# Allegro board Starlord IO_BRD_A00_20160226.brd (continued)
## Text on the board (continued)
User.28: ByImpedance:100.0@_REF_L1=("nil(L1)")|_REF_L6=("4.0/10.0(L6)")|Type="DP"|_REF_L4=("4.0/6.5(L4)")|_REF_L3=("4.0/6.5(L3)" "4.0/10.0(L3)")|imp="100.0"|_REF_L8=("nil(L8)") | ByImpedance:33.0@_REF_L1=("8.0(L1)")|_REF_L6=("9.0(L6)")|Type="SE"|_REF_L4=("11.0(L4)")|_REF_L3=("11.0(L3)" "9.0(L3)")|imp="33.0"|_REF_L8=("8.0(L8)") | ByImpedance:35.0@_REF_L1=("7.5(L1)")|_REF_L6=("8.5(L6)")|Type="SE"|_REF_L4=("10.0(L4)")|_REF_L3=("10.0(L3)" "8.5(L3)")|imp="35.0"|_REF_L8=("7.5(L8)") | ByImpedance:37.5@_REF_L1=("6.5(L1)")|_REF_L6=("7.5(L6)")|Type="SE"|_REF_L4=("9.0(L4)")|_REF_L3=("7.5(L3)" "9.0(L3)")|imp="37.5"|_REF_L8=("6.5(L8)") | ByImpedance:40.0@_REF_L1=("6.0(L1)")|_REF_L6=("6.5(L6)")|Type="SE"|_REF_L4=("8.0(L4)")|_REF_L3=("6.5(L3)" "8.0(L3)")|imp="40.0"|_REF_L8=("6.0(L8)") | ByImpedance:45.0@_REF_L1=("4.5(L1)")|_REF_L6=("5.0(L6)")|Type="SE"|_REF_L4=("6.5(L4)")|_REF_L3=("6.5(L3)" "5.0(L3)")|imp="45.0"|_REF_L8=("4.5(L8)") | ByImpedance:50.0@_REF_L1=("3.5(L1)")|_REF_L6=("4.0(L6)")|Type="SE"|_REF_L4=("5.0(L4)")|_REF_L3=("4.0(L3)" "5.0(L3)")|imp="50.0"|_REF_L8=("3.5(L8)") | ByImpedance:55.0@_REF_L1=("nil(L1)")|_REF_L6=("nil(L6)")|Type="SE"|_REF_L4=("4.0(L4)")|_REF_L3=("4.0(L3)")|imp="55.0"|_REF_L8=("nil(L8)") | ByImpedance:60.0@_REF_L1=("7.5/4.0(L1)")|_REF_L6=("9.5/4.5(L6)")|Type="DP"|_REF_L4=("10.5/4.5(L4)")|_REF_L3=("10.5/4.5(L3)" "9.5/4.5(L3)")|imp="60.0"|_REF_L8=("7.5/4.0(L8)") | ByImpedance:63.0@_REF_L1=("7.0/4.5(L1)")|_REF_L6=("8.5/4.0(L6)")|Type="DP"|_REF_L4=("9.5/4.0(L4)")|_REF_L3=("8.5/4.0(L3)" "9.5/4.0(L3)")|imp="63.0"|_REF_L8=("7.0/4.5(L8)") | ByImpedance:70.0@_REF_L1=("6.0/5.0(L1)")|_REF_L6=("7.0/5.0(L6)")|Type="DP"|_REF_L4=("8.5/5.0(L4)")|_REF_L3=("7.0/5.0(L3)" "8.5/5.0(L3)")|imp="70.0"|_REF_L8=("6.0/5.0(L8)") | ByImpedance:72.0@_REF_L1=("5.5/4.5(L1)")|_REF_L6=("6.5/4.5(L6)")|Type="DP"|_REF_L4=("7.5/5.0(L4)")|_REF_L3=("7.5/5.0(L3)" "6.5/4.5(L3)")|imp="72.0"|_REF_L8=("5.5/4.5(L8)") | ByImpedance:75.0@_REF_L1=("5.0/4.5(L1)")|_REF_L6=("6.0/4.5(L6)")|Type="DP"|_REF_L4=("7.0/5.0(L4)")|_REF_L3=("7.0/5.0(L3)" "6.0/4.5(L3)")|imp="75.0"|_REF_L8=("5.0/4.5(L8)") | ByImpedance:80.0@_REF_L1=("4.5/5.0(L1)")|_REF_L6=("5.5/5.0(L6)")|Type="DP"|_REF_L4=("6.0/5.0(L4)")|_REF_L3=("5.5/5.0(L3)" "6.0/5.0(L3)")|imp="80.0"|_REF_L8=("4.5/5.0(L8)") | ByImpedance:83.0@_REF_L1=("3.5/4.0(L1)")|_REF_L6=("5.0/4.0(L6)")|Type="DP"|_REF_L4=("5.5/4.5(L4)")|_REF_L3=("5.5/4.5(L3)" "5.0/4.0(L3)")|imp="83.0"|_REF_L8=("3.5/4.0(L8)") | ByImpedance:85.0@_REF_L1=("4.0/5.0(L1)")|_REF_L6=("5.0/5.5(L6)")|Type="DP"|_REF_L4=("5.5/5.0(L4)")|_REF_L3=("5.5/5.0(L3)" "5.0/5.5(L3)")|imp="85.0"|_REF_L8=("4.0/5.0(L8)") | ByImpedance:88.0@_REF_L1=("4.0/7.0(L1)")|_REF_L6=("4.0/4.0(L6)")|Type="DP"|_REF_L4=("5.0/5.0(L4)")|_REF_L3=("4.0/4.0(L3)" "5.0/5.0(L3)")|imp="88.0"|_REF_L8=("4.0/7.0(L8)") | ByImpedance:90.0@_REF_L1=("4.0/8.0(L1)" "3.5/6.0(L1)")|_REF_L6=("4.0/4.5(L6)")|Type="DP"|_REF_L4=("5.0/6.0(L4)")|_REF_L3=("5.0/6.0(L3)" "4.0/4.5(L3)")|imp="90.0"|_REF_L8=("4.0/8.0(L8)" "3.5/6.0(L8)") | LayerIndex:nil | Source:8-1.0-16f.xls | artWorks:("_REF_L3" "_REF_L6" "_REF_L4" "_REF_L8" "_REF_L1") | gtImpOutlineUsed:BOARD GEOMETRY/OUTLINE
User.29: Board Accuracy Check,Jan 13 16:18:50 2016,Passed | Dummy-Static-No Shape On Layer Check,Jan 13 16:18:50 2016,Passed | Split Plane Check,Oct 21 14:08:23 2015,Passed
User.31: This gerber is just for your reference to find the DP impedance traces in layer L1. | DP IMPEDANCE TABLE: L1 | * - Denotes that this Impedance | is NOT used | IMP(Ohm) | *60.0 | *63.0 | *70.0 | *72.0 | *75.0 | *80.0 | *83.0 | 85.0 | *88.0 | *90.0 | *100.0 | WIDTH(mils) | 7.5/4.0 | 7.0/4.5 | 6.0/5.0 | 5.5/4.5 | 5.0/4.5 | 4.5/5.0 | 3.5/4.0 | 4.0/5.0 | 4.0/7.0 | 4.0/8.0 | 3.5/6.0 | nil | TYPE | DP
User.33: This gerber is just for your reference to find the SE impedance traces in layer L1. | SE IMPEDANCE TABLE: L1 | * - Denotes that this Impedance | is NOT used | IMP(Ohm) | *33.0 | *35.0 | *37.5 | *40.0 | *45.0 | *50.0 | *55.0 | WIDTH(mils) | 8.0 | 7.5 | 6.5 | 6.0 | 4.5 | 3.5 | nil | TYPE | SE
User.35: This gerber is just for your reference to find the DP impedance traces in layer L3. | DP IMPEDANCE TABLE: L3 | * - Denotes that this Impedance | is NOT used | IMP(Ohm) | *60.0 | *63.0 | *70.0 | *72.0 | *75.0 | *80.0 | *83.0 | *85.0 | *88.0 | *90.0 | *100.0 | WIDTH(mils) | 10.5/4.5 | 9.5/4.5 | 8.5/4.0 | 9.5/4.0 | 7.0/5.0 | 8.5/5.0 | 7.5/5.0 | 6.5/4.5 | 6.0/4.5 | 5.5/5.0 | 6.0/5.0 | 5.5/4.5 | 5.0/4.0 | 5.0/5.5 | 4.0/4.0 | 5.0/5.0 | 5.0/6.0 | 4.0/4.5 | 4.0/6.5 | 4.0/10.0 | TYPE | DP
User.37: This gerber is just for your reference to find the SE impedance traces in layer L3. | SE IMPEDANCE TABLE: L3 | * - Denotes that this Impedance | is NOT used | IMP(Ohm) | *33.0 | *35.0 | *37.5 | *40.0 | *45.0 | *50.0 | *55.0 | WIDTH(mils) | 11.0 | 9.0 | 10.0 | 8.5 | 7.5 | 6.5 | 8.0 | 5.0 | 4.0 | TYPE | SE
User.39: This gerber is just for your reference to find the DP impedance traces in layer L4. | DP IMPEDANCE TABLE: L4 | * - Denotes that this Impedance | is NOT used | IMP(Ohm) | *60.0 | *63.0 | *70.0 | *72.0 | *75.0 | *80.0 | *83.0 | *85.0 | *88.0 | *90.0 | *100.0 | WIDTH(mils) | 10.5/4.5 | 9.5/4.0 | 8.5/5.0 | 7.5/5.0 | 7.0/5.0 | 6.0/5.0 | 5.5/4.5 | 5.5/5.0 | 5.0/5.0 | 5.0/6.0 | 4.0/6.5 | TYPE | DP
User.41: This gerber is just for your reference to find the SE impedance traces in layer L4. | SE IMPEDANCE TABLE: L4 | * - Denotes that this Impedance | is NOT used | IMP(Ohm) | *33.0 | *35.0 | *37.5 | *40.0 | *45.0 | *50.0 | *55.0 | WIDTH(mils) | 11.0 | 10.0 | 9.0 | 8.0 | 6.5 | 5.0 | 4.0 | TYPE | SE
User.43: This gerber is just for your reference to find the DP impedance traces in layer L6. | DP IMPEDANCE TABLE: L6 | * - Denotes that this Impedance | is NOT used | IMP(Ohm) | *60.0 | *63.0 | *70.0 | *72.0 | *75.0 | *80.0 | *83.0 | 85.0 | *88.0 | *90.0 | *100.0 | WIDTH(mils) | 9.5/4.5 | 8.5/4.0 | 7.0/5.0 | 6.5/4.5 | 6.0/4.5 | 5.5/5.0 | 5.0/4.0 | 5.0/5.5 | 4.0/4.0 | 4.0/4.5 | 4.0/10.0 | TYPE | DP
User.45: Note:Refer to DRILL layer for ELLIPSE drill direction | FIGURE | SIZE | 10.0 | 16.0 | 37.0 | 40.0 | 95.0 | 46.0 | 65.0 | 86.0 | 115.0 | 75.0x26.0 | 91.0x36.0 | 95.0x36.0 | 146.0x115.0 | DRILL CHART: TOP to BOTTOM | ALL UNITS ARE IN MILS | PLATED | NON-PLATED | QTY | 370 | 16 | 4 | 11 | 2 | 1 | This gerber is just for your reference to find the SE impedance traces in layer L6. | This gerber is just for your reference to find the SE impedance traces in layer L8. | This gerber is just for your reference to find the DP impedance traces in layer L8. | DP IMPEDANCE TABLE: L8 | SE IMPEDANCE TABLE: L6 | SE IMPEDANCE TABLE: L8 | * - Denotes that this Impedance | is NOT used | Model | Starlord13 R I/O | PCB_NO | 15915 | VER. | SC | IMP(Ohm) | *33.0 | *60.0 | *35.0 | *63.0 | *37.5 | *70.0 | *40.0 | *72.0 | *45.0 | *75.0 | *50.0 | *80.0 | *55.0 | *83.0 | 85.0 | *88.0 | *90.0 | *100.0 | Layer | DRILL | L1 | L2GND | L3 | L4 | TMASK | TPLACE | TSILK | TSMD | Designer | JAZZ_XUE | WIDTH(mils) | 8.0 | 9.0 | 7.5 | 8.5 | 6.5 | 6.0 | 4.5 | 5.0 | 3.5 | 4.0 | nil | 7.5/4.0 | 7.0/4.5 | 6.0/5.0 | 5.5/4.5 | 5.0/4.5 | 4.5/5.0 | 3.5/4.0 | 4.0/5.0 | 4.0/7.0 | 4.0/8.0 | 3.5/6.0 | TYPE | SE | Date | 01/13/2016 | DP | BMASK | BPLACE | BSILK | BSMD | L5VCC | L6 | L7GND | L8
